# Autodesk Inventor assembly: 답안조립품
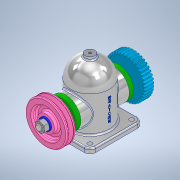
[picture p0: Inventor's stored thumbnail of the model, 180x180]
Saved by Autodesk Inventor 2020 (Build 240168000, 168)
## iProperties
Created: 2021-07
Part Number: 답안조립품
Document SubType Name: Assembly
Designer: Owner
Author: Owner
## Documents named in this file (14)
- C:\Users\Owner\Desktop\710716V1002\답안조립품.iam
- C:\Users\Owner\Desktop\710716V1002\본체.ipt
- C:\Users\Owner\Desktop\710716V1002\V-벨트풀리.ipt
- V-벨트풀리.ipt
- C:\Users\Owner\Desktop\710716V1002\너트 M12x1.25.ipt
- C:\Users\Owner\Desktop\710716V1002\베어링 6203.ipt
- C:\Users\Owner\Desktop\710716V1002\볼트 M4.ipt
- C:\Users\Owner\Desktop\710716V1002\부시.ipt
- C:\Users\Owner\Desktop\710716V1002\스퍼기어.ipt
- C:\Users\Owner\Desktop\710716V1002\오일 실 26 38 8.ipt
- C:\Users\Owner\Desktop\710716V1002\와셔 12x24.ipt
- C:\Users\Owner\Desktop\710716V1002\축.ipt
- C:\Users\Owner\Desktop\710716V1002\커버.ipt
- C:\Users\Owner\Desktop\710716V1002\키 5x5x12.ipt
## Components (1 placed, 1 different names)
1. V-벨트풀리:1
